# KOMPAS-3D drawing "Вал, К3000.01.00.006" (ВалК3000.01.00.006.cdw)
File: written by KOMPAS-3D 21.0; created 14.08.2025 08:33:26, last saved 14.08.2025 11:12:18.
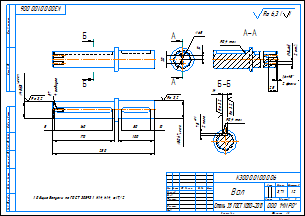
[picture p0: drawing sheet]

Sheet 1: A3, landscape

Document properties: Автор: admin; Знак неуказанной шероховатости: 4; Параметр неуказанной шероховатости: Ra 6,3; Масса: 3.712265

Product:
- Part/product: Вал  | designation К3000.01.00.006
    Материал: Сталь 35 ГОСТ 1050-2013 (density 7826 kg/m3)
    Масса: 3.712265
  - Body: Тело 1
      Масса: 3.712554

Title block, sheet 1: Наименование: Вал; designation: К3000.01.00.006; Материал: Сталь 35 ГОСТ 1050-2013; Масса: 3,71; Количество листов документа: 1; organisation: ООО "МИРО"; Форматы листов документа: A3; stored path: C:\Users\ShavarinML\Desktop\Стапель\2D\ВалК3000.01.00.006.cdw

Views: Проекционный вид 4, Проекционный вид 5, Проекционный вид 6, Разрез А-А, Разрез Б-Б
Referenced files in C:\Users\ShavarinML\Desktop\Стапель\Из трубы\: Вал 2.m3d
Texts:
  Ra 3,2
  max
  Ra 6,3
  Ra 6,3 ( )
  К3000.01.00.006 Вал
Dimensions and other numbers on the sheet: 65; 20; 10; 280; 170; 100; 45; 50; 160; 5; 80; 7; 4 радиуса; 25; 1,6; 2 фаски; -6H; 8; 2 отв.; 0,4; 7,5; 2 паза; 14; 1:2; 1; 3,71

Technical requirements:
  Общие допуски по ГОСТ 30893.1: H14, h14,   IT/2.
